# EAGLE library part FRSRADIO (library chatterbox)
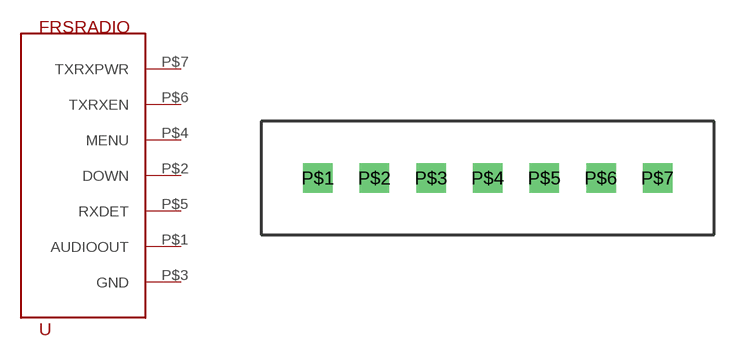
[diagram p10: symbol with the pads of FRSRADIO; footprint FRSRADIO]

Designator prefix -

## FRSRADIO-1  [FRSRADIO]
P$1  AUDIOOUT
P$2  DOWN
P$3  GND
P$4  MENU
P$5  RXDET
P$6  TXRXEN
P$7  TXRXPWR

## Footprint FRSRADIO (pad centres in mm)
drill 0.813 square: P$1 -7.62,0; P$2 -5.08,0; P$3 -2.54,0; P$4 0,0; P$5 2.54,0; P$6 5.08,0; P$7 7.62,0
